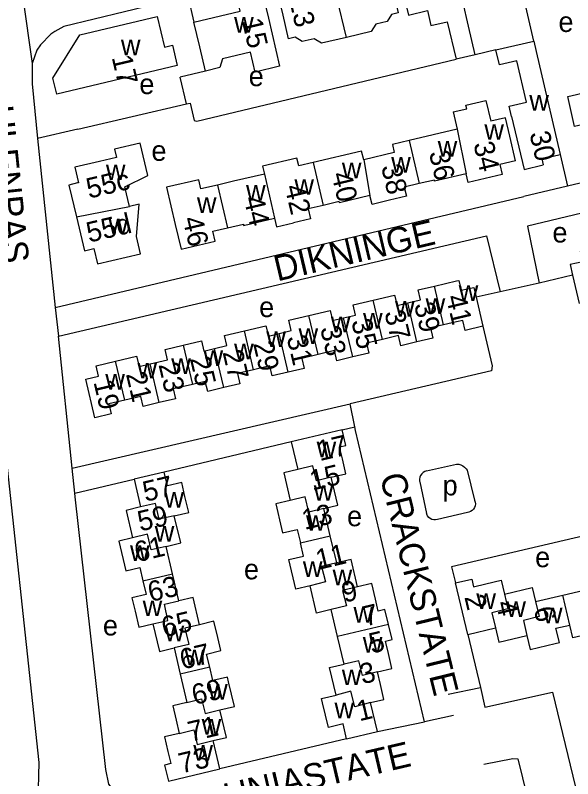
# Model space of a CAD drawing. Extents: x 157646 to 159241, y 379213 to 381217.
# Drawn here: x 158413 to 158522.9, y 380508.3 to 380658.9 of the extents above; entities that cross this region are included whole.
import ezdxf

# ---------------------------------------------------------------- set-up
doc = ezdxf.new("R2010")
doc.units = 0
for name, color, linetype in [('BLT_Basislijn', 7, 'Continuous'), ('BLT_Bebouwing', 7, 'Continuous'), ('BLT_Centroide', 7, 'Continuous'), ('BLT_Huisnummer', 7, 'Continuous'), ('BLT_Huisnummer_ tussenligend', 7, 'Continuous'), ('BLT_Onderverdeling_panden', 7, 'Continuous'), ('BLT_Straatnaam', 7, 'Continuous'), ('BLT_Vlakafsluiter', 7, 'Continuous')]:
    doc.layers.add(name, color=color, linetype=linetype)

msp = doc.modelspace()

# ---------------------------------------------------------------- linework, layer by layer
at = {"layer": 'BLT_Basislijn'}
for p, q in [((158515.2, 380653.77), (158512.79, 380664.6)), ((158447.01, 380662.59), (158448.21, 380657.51)), ((158507.75, 380652.05), (158503.65, 380651.07)), ((158450.49, 380647.86), (158445.49, 380646.66)), ((158446.72, 380641.37), (158445.49, 380646.66)), ((158425.3, 380636.36), (158446.72, 380641.37)), ((158425.3, 380636.36), (158417.35, 380634.52)), ((158417.35, 380634.52), (158420.82, 380601.23)), ((158520.42, 380631.37), (158521.88, 380625.14)), ((158420.82, 380601.23), (158513.28, 380623.09)), ((158522.88, 380607.57), (158516.27, 380606.04)), ((158516.27, 380606.04), (158508.57, 380604.3)), ((158508.57, 380604.3), (158503.84, 380603.23)), ((158420.82, 380601.23), (158421.53, 380595.56)), ((158424.19, 380569.51), (158421.53, 380595.56)), ((158424.19, 380569.51), (158479.03, 380582.24)), ((158479.92, 380577.68), (158479.03, 380582.24)), ((158477.44, 380577.11), (158479.92, 380577.68)), ((158467.41, 380574.73), (158442.32, 380568.77)), ((158424.7, 380564.63), (158424.19, 380569.51)), ((158494.09, 380569.01), (158500, 380570.34)), ((158502.08, 380569.12), (158503.55, 380563.21)), ((158424.7, 380564.63), (158436.4, 380567.37)), ((158492.72, 380566.81), (158494.06, 380560.62)), ((158502.13, 380560.82), (158496.22, 380559.42)), ((158502.23, 380536.73), (158504.69, 380526.29)), ((158498.34, 380524.99), (158504.69, 380526.29)), ((158499.39, 380520.79), (158493.68, 380519.49)), ((158484.38, 380517.58), (158493.68, 380519.49)), ((158478.3, 380516.14), (158453.31, 380510.22))]:
    msp.add_line(p, q, dxfattribs=at)
for points in [[(158447.01, 380662.59), (158446.7, 380662.51), (158440.52, 380661), (158422.54, 380656.66), (158420.79, 380655.65), (158419.96, 380655.15), (158417.95, 380653.03), (158417.26, 380651.95), (158416.28, 380649.31)], [(158416.28, 380649.31), (158416.34, 380645.36), (158417.35, 380634.52)], [(158446.72, 380641.37), (158447.44, 380641.53), (158448.28, 380638.07), (158448.76, 380637.97), (158499.88, 380650.19)], [(158539.21, 380629.26), (158538.5, 380629.1), (158521.88, 380625.14)], [(158521.88, 380625.14), (158513.28, 380623.09)], [(158538.4, 380623.1), (158513.99, 380617.28), (158516.27, 380606.04)], [(158421.53, 380595.56), (158505.88, 380615.34), (158508.57, 380604.3)], [(158505.2, 380597.51), (158507.01, 380589.72), (158506.85, 380588.76), (158479.03, 380582.24)], [(158382, 380486.03), (158394.7, 380478.15), (158397.65, 380476.58), (158401, 380475.76), (158402.65, 380477.1), (158414.74, 380494.85), (158416.53, 380498.98), (158417.47, 380503.76), (158417.68, 380511.48), (158409.95, 380583.17)], [(158493.68, 380519.49), (158480.06, 380576.99), (158479.92, 380577.68)], [(158500, 380570.34), (158500.43, 380570.31), (158500.85, 380570.19), (158501.23, 380570.01), (158501.58, 380569.75), (158501.87, 380569.43), (158502.08, 380569.12)], [(158494.09, 380569.01), (158493.73, 380568.89), (158493.4, 380568.69), (158493.12, 380568.43), (158492.9, 380568.11), (158492.75, 380567.76), (158492.68, 380567.39), (158492.69, 380567), (158492.72, 380566.81)], [(158432.15, 380506.31), (158431.46, 380507.21), (158430.83, 380510.09), (158424.78, 380563.88), (158424.7, 380564.63)], [(158503.55, 380563.21), (158503.66, 380562.86), (158503.69, 380562.49), (158503.65, 380562.12), (158503.52, 380561.78), (158503.33, 380561.46), (158503.07, 380561.2), (158502.76, 380561), (158502.41, 380560.86), (158502.13, 380560.82)], [(158496.22, 380559.42), (158495.86, 380559.35), (158495.49, 380559.36), (158495.13, 380559.44), (158494.8, 380559.6), (158494.51, 380559.83), (158494.28, 380560.12), (158494.12, 380560.45), (158494.06, 380560.62)], [(158534.42, 380558.37), (158533.32, 380558.11), (158498.97, 380550.09), (158499.8, 380546.9)], [(158504.69, 380526.29), (158505.57, 380522.37), (158518.89, 380525.34), (158527.39, 380490.29), (158538.07, 380492.65)], [(158505.34, 380511.18), (158511.1, 380512.31), (158512.05, 380512.19), (158518.7, 380485.21)]]:
    msp.add_lwpolyline(points, dxfattribs=at)
at = {"layer": 'BLT_Bebouwing'}
for p, q in [((158507.75, 380652.05), (158515.2, 380653.77)), ((158515.2, 380653.77), (158515.66, 380651.69)), ((158503.65, 380651.07), (158499.88, 380650.19)), ((158515.66, 380651.69), (158520.42, 380631.37)), ((158499.32, 380639.8), (158501.99, 380640.42)), ((158501.99, 380640.42), (158501.83, 380641.12)), ((158499.32, 380639.8), (158500.13, 380636.36)), ((158510.84, 380638.92), (158513.29, 380628.47)), ((158516.82, 380630.52), (158520.42, 380631.37)), ((158516.82, 380630.52), (158517.09, 380629.36)), ((158513.29, 380628.47), (158517.09, 380629.36)), ((158462.11, 380627.55), (158455.98, 380626.11)), ((158522.88, 380607.57), (158524.19, 380602.04)), ((158503.84, 380603.23), (158505.2, 380597.51)), ((158477.44, 380577.11), (158467.41, 380574.73)), ((158467.41, 380574.73), (158468.69, 380569.29)), ((158442.32, 380568.77), (158436.4, 380567.37)), ((158436.4, 380567.37), (158437.7, 380561.88)), ((158445.24, 380543.4), (158443.99, 380548.68)), ((158502.23, 380536.73), (158499.8, 380546.9)), ((158520.92, 380544.49), (158526.26, 380545.76)), ((158515.58, 380543.21), (158520.92, 380544.49)), ((158476.53, 380536.32), (158475.27, 380541.64)), ((158502.23, 380536.73), (158507.67, 380538.02)), ((158477.82, 380530.89), (158476.53, 380536.32)), ((158444.28, 380534.08), (158445.51, 380528.9)), ((158478.3, 380516.14), (158484.38, 380517.58)), ((158453.31, 380510.22), (158451.99, 380515.8)), ((158443.18, 380507.82), (158453.31, 380510.22))]:
    msp.add_line(p, q, dxfattribs=at)
for points in [[(158503.65, 380651.07), (158502.33, 380656.72), (158501.2, 380661.59), (158500, 380661.31), (158497.74, 380660.78), (158495.35, 380671.01), (158488.06, 380669.31), (158489.2, 380664.44), (158490.49, 380658.89), (158494.25, 380659.77), (158494.94, 380656.81), (158498.16, 380657.56), (158499.88, 380650.19)], [(158476.28, 380662.89), (158478.68, 380663.46), (158479.46, 380664.72), (158479.17, 380665.96), (158480.15, 380667.54), (158486.19, 380668.96), (158487.34, 380664.1), (158488.46, 380659.33), (158487.15, 380659.02), (158486.29, 380657.64), (158484.08, 380657.11), (158483.17, 380655.65), (158478.26, 380654.49)], [(158478.26, 380654.49), (158473.34, 380653.33), (158471.93, 380654.21), (158469.56, 380653.65), (158468.17, 380654.51), (158466.87, 380654.21), (158465.77, 380658.9), (158464.62, 380663.77), (158470.52, 380665.15), (158472.03, 380664.22), (158472.3, 380663.06), (158473.59, 380662.26), (158476.28, 380662.89)], [(158448.21, 380657.51), (158457.33, 380659.66), (158456.78, 380662), (158461.73, 380663.16), (158462.88, 380658.3), (158465.11, 380648.79), (158460.25, 380647.65), (158459.33, 380651.56), (158453.86, 380650.27), (158453.33, 380648.53), (158450.49, 380647.86)], [(158425.69, 380655.01), (158440.98, 380658.64), (158442.41, 380652.57), (158443.97, 380652.93), (158444.93, 380648.96), (158421.15, 380643.31), (158420.39, 380646.45), (158425.69, 380655.01)], [(158450.49, 380647.86), (158449.36, 380652.65), (158448.21, 380657.51)], [(158510.84, 380638.92), (158510.37, 380640.92), (158513.8, 380641.73), (158511.89, 380649.89), (158508.44, 380649.08), (158507.75, 380652.05)], [(158538.75, 380631.2), (158531, 380629.4), (158528.94, 380638.26), (158523.27, 380636.94), (158521.9, 380642.83), (158531.25, 380645)], [(158501.83, 380641.12), (158505.77, 380642.05), (158506.73, 380637.96)], [(158509.62, 380638.63), (158506.73, 380637.96)], [(158511.61, 380630.14), (158510.47, 380635.01), (158509.62, 380638.63)], [(158500.13, 380636.36), (158490.62, 380634.13)], [(158490.62, 380634.13), (158487.34, 380633.36), (158487.71, 380631.78), (158481.68, 380630.35)], [(158434.55, 380624.99), (158439.13, 380627.24), (158437.63, 380633.63), (158432.54, 380632.43), (158432.92, 380630.81)], [(158481.68, 380630.35), (158481.27, 380632.07), (158471.71, 380629.82)], [(158432.92, 380630.81), (158429.57, 380630.03), (158424.7, 380628.88), (158425.42, 380625.83), (158425.23, 380625.78), (158423.55, 380625.38), (158425.02, 380619.1)], [(158471.71, 380629.82), (158468.87, 380629.15), (158468.51, 380630.7), (158461.74, 380629.12), (158462.11, 380627.55)], [(158511.61, 380630.14), (158508.54, 380629.42), (158508.99, 380627.47), (158505.65, 380626.68)], [(158501.86, 380627.59), (158495.62, 380626.12), (158495.66, 380626.36)], [(158505.65, 380626.68), (158502.26, 380625.89), (158501.86, 380627.59)], [(158435.47, 380621.12), (158434.55, 380624.99)], [(158452.84, 380625.37), (158449.59, 380624.6), (158449.16, 380626.43), (158442.8, 380624.93), (158444.53, 380617.57), (158445.68, 380612.71), (158452.4, 380614.29), (158451.94, 380616.25), (158454.81, 380616.92)], [(158455.98, 380626.11), (158452.84, 380625.37)], [(158492.6, 380625.65), (158489.69, 380624.97), (158490.12, 380623.15), (158486.74, 380622.36)], [(158495.66, 380626.36), (158492.59, 380625.65)], [(158476.85, 380622.12), (158473.68, 380621.37)], [(158482.91, 380623.31), (158476.9, 380621.89), (158476.85, 380622.12)], [(158486.74, 380622.36), (158483.33, 380621.55), (158482.91, 380623.31)], [(158425.02, 380619.1), (158426.6, 380612.42), (158428.49, 380612.86), (158429.21, 380609.81), (158437.66, 380611.8), (158436.86, 380615.21), (158437.4, 380621.58), (158435.47, 380621.12)], [(158473.68, 380621.37), (158470.76, 380620.68), (158471.22, 380618.72), (158467.86, 380617.93)], [(158454.81, 380616.92), (158457.97, 380617.67)], [(158457.97, 380617.67), (158458.01, 380617.41), (158464.07, 380618.87)], [(158464.07, 380618.87), (158464.48, 380617.14), (158467.86, 380617.93)], [(158528.35, 380613.18), (158524.39, 380612.24), (158524.86, 380610.25), (158522.38, 380609.67), (158522.88, 380607.57)], [(158490.35, 380602.12), (158492.86, 380602.72), (158492.4, 380604.69), (158495.62, 380605.45)], [(158495.62, 380605.45), (158500, 380606.49), (158500.45, 380606.57), (158500.91, 380604.61), (158503.38, 380605.19), (158503.84, 380603.23)], [(158477.72, 380599.16), (158480.06, 380599.71), (158479.58, 380601.73), (158483.56, 380602.67)], [(158483.56, 380602.67), (158487.77, 380603.67), (158488.25, 380601.63), (158490.35, 380602.12)], [(158464.99, 380596.09), (158467.4, 380596.66), (158466.92, 380598.71), (158470.86, 380599.65)], [(158470.86, 380599.65), (158475.08, 380600.64), (158475.56, 380598.64), (158477.72, 380599.16)], [(158505.2, 380597.51), (158501.71, 380596.68), (158501.24, 380598.65), (158499.99, 380598.4), (158497.43, 380597.79)], [(158452.26, 380593.14), (158454.72, 380593.72), (158454.25, 380595.69), (158458.17, 380596.62)], [(158458.17, 380596.62), (158462.41, 380597.62), (158462.89, 380595.6), (158464.99, 380596.09)], [(158497.43, 380597.79), (158494.86, 380597.18), (158495.33, 380595.19), (158492.17, 380594.44)], [(158485.39, 380594.93), (158482.24, 380594.19), (158482.7, 380592.23), (158479.54, 380591.48)], [(158492.17, 380594.44), (158489, 380593.69), (158488.53, 380595.68), (158485.39, 380594.93)], [(158439.56, 380590.09), (158443, 380590.91), (158442.52, 380592.93), (158446.09, 380593.77)], [(158446.09, 380593.77), (158449.67, 380594.62), (158450.13, 380592.64), (158452.26, 380593.14)], [(158472.68, 380591.94), (158469.47, 380591.18), (158469.93, 380589.21), (158466.8, 380588.46)], [(158479.54, 380591.48), (158476.37, 380590.73), (158475.9, 380592.71), (158472.68, 380591.94)], [(158434.58, 380582.96), (158431.44, 380582.22), (158431.91, 380580.22), (158428.68, 380579.46), (158426.88, 380587.08), (158429.39, 380587.68), (158428.9, 380589.74), (158432.76, 380590.65)], [(158432.76, 380590.65), (158436.9, 380591.63), (158437.39, 380589.58), (158439.56, 380590.09)], [(158459.98, 380588.96), (158456.77, 380588.2), (158457.26, 380586.18), (158454.09, 380585.43)], [(158466.8, 380588.46), (158463.65, 380587.72), (158463.18, 380589.72), (158459.98, 380588.96)], [(158447.92, 380586.06), (158444.08, 380585.15), (158444.54, 380583.21), (158441.36, 380582.46)], [(158454.09, 380585.43), (158450.92, 380584.68), (158450.45, 380586.66), (158447.92, 380586.06)], [(158441.36, 380582.46), (158438.19, 380581.71), (158437.72, 380583.7), (158434.58, 380582.96)], [(158477.47, 380571.37), (158476.91, 380573.72), (158478.17, 380574.02), (158477.44, 380577.11)], [(158475.29, 380567.73), (158478.17, 380568.41), (158477.47, 380571.37)], [(158468.69, 380569.29), (158465.9, 380568.63), (158467.18, 380563.19)], [(158446.44, 380563.95), (158445.79, 380566.69), (158442.97, 380566.02), (158442.32, 380568.77)], [(158473.82, 380561.57), (158476.59, 380562.23), (158475.29, 380567.73)], [(158444.33, 380560.15), (158447.18, 380560.82), (158446.44, 380563.95)], [(158467.18, 380563.19), (158464.33, 380562.52), (158465.48, 380557.65), (158465.69, 380556.76), (158468.57, 380557.45), (158469.19, 380554.83)], [(158437.7, 380561.88), (158434.82, 380561.2), (158436.1, 380555.81)], [(158475.09, 380556.22), (158473.82, 380561.57)], [(158442.7, 380554.11), (158445.6, 380554.8), (158444.33, 380560.15)], [(158436.1, 380555.81), (158433.38, 380555.16), (158434.77, 380549.29), (158437.52, 380549.94), (158438.15, 380547.29)], [(158476.36, 380550.88), (158475.09, 380556.22)], [(158471.12, 380546.34), (158468.29, 380545.67), (158466.9, 380551.52), (158469.81, 380552.21), (158469.19, 380554.83)], [(158443.99, 380548.68), (158442.7, 380554.11)], [(158480.47, 380546.12), (158479.18, 380551.55), (158476.36, 380550.88)], [(158438.15, 380547.29), (158438.77, 380544.65), (158435.98, 380543.99), (158436.6, 380541.35)], [(158484, 380543.7), (158483.27, 380546.78), (158480.47, 380546.12)], [(158499.8, 380546.9), (158502.97, 380547.64), (158503.32, 380546.16), (158505.74, 380546.74)], [(158505.74, 380546.74), (158508.77, 380547.46), (158509.43, 380544.68)], [(158475.27, 380541.64), (158472.39, 380540.96), (158471.12, 380546.34)], [(158509.43, 380544.68), (158514.92, 380545.99), (158515.58, 380543.21)], [(158449.32, 380538.66), (158448.05, 380544.06), (158445.24, 380543.4)], [(158486.57, 380538.7), (158485.87, 380541.63), (158484.56, 380541.33), (158484, 380543.7)], [(158436.6, 380541.35), (158437.36, 380538.17), (158440.11, 380538.83)], [(158452.92, 380536.12), (158452.16, 380539.33), (158449.32, 380538.66)], [(158530.6, 380540.6), (158531.27, 380537.77), (158525.56, 380536.4), (158525.49, 380536.67), (158522.93, 380536.08), (158522.32, 380538.6)], [(158440.11, 380538.83), (158441.4, 380533.39), (158444.28, 380534.08)], [(158486.56, 380532.96), (158485.97, 380535.45), (158487.26, 380535.76), (158486.57, 380538.7)], [(158507.67, 380538.02), (158508.33, 380535.24), (158513.87, 380536.55)], [(158513.87, 380536.55), (158514.53, 380533.76), (158519.4, 380534.93), (158520.27, 380535.13), (158519.59, 380537.95), (158522.32, 380538.6)], [(158451.33, 380530.28), (158450.71, 380532.88), (158453.53, 380533.55), (158452.92, 380536.12)], [(158484.38, 380529.36), (158487.25, 380530.04), (158486.56, 380532.96)], [(158453.32, 380521.86), (158456.18, 380522.54), (158455.02, 380527.4), (158454.8, 380528.35), (158451.94, 380527.67), (158451.33, 380530.28)], [(158476.24, 380524.78), (158474.96, 380530.21), (158477.82, 380530.89)], [(158445.51, 380528.9), (158446.82, 380523.35)], [(158484.97, 380526.85), (158484.38, 380529.36)], [(158483.03, 380523.29), (158485.67, 380523.91), (158484.97, 380526.85)], [(158478.3, 380516.14), (158477.6, 380519.09), (158474.71, 380518.4), (158473.56, 380523.27), (158473.36, 380524.1), (158476.24, 380524.78)], [(158446.82, 380523.35), (158444.02, 380522.68), (158444.7, 380519.82)], [(158484.38, 380517.58), (158483.03, 380523.29)], [(158451.99, 380515.8), (158454.61, 380516.43), (158453.32, 380521.86)], [(158444.7, 380519.82), (158445.32, 380517.21)], [(158445.32, 380517.21), (158442.39, 380516.52), (158443.06, 380513.69)], [(158443.06, 380513.69), (158443.63, 380511.29), (158442.41, 380510.99), (158443.18, 380507.82)]]:
    msp.add_lwpolyline(points, dxfattribs=at)
at = {"layer": 'BLT_Onderverdeling_panden'}
for p, q in [((158478.26, 380654.49), (158476.28, 380662.89)), ((158500.13, 380636.36), (158501.86, 380627.59)), ((158490.62, 380634.13), (158492.6, 380625.65)), ((158471.71, 380629.82), (158473.68, 380621.37)), ((158481.68, 380630.35), (158482.91, 380623.31)), ((158462.11, 380627.55), (158464.07, 380618.87)), ((158452.84, 380625.37), (158454.81, 380616.92)), ((158425.02, 380619.1), (158435.47, 380621.12)), ((158497.43, 380597.79), (158495.62, 380605.45)), ((158485.39, 380594.93), (158483.56, 380602.67)), ((158492.17, 380594.44), (158490.35, 380602.12)), ((158472.68, 380591.94), (158470.86, 380599.65)), ((158479.54, 380591.48), (158477.72, 380599.16)), ((158459.98, 380588.96), (158458.17, 380596.62)), ((158466.8, 380588.46), (158464.99, 380596.09)), ((158446.09, 380593.77), (158447.92, 380586.06)), ((158454.09, 380585.43), (158452.26, 380593.14)), ((158434.58, 380582.96), (158432.76, 380590.65)), ((158441.36, 380582.46), (158439.56, 380590.09)), ((158469.19, 380554.83), (158475.09, 380556.22)), ((158438.15, 380547.29), (158443.99, 380548.68)), ((158522.32, 380538.6), (158520.92, 380544.49)), ((158486.57, 380538.7), (158476.53, 380536.32)), ((158451.33, 380530.28), (158445.51, 380528.9))]:
    msp.add_line(p, q, dxfattribs=at)
for points in [[(158475.29, 380567.73), (158472.4, 380567.01), (158471.64, 380569.99), (158468.69, 380569.29)], [(158473.82, 380561.57), (158470.86, 380560.87), (158470.14, 380563.9), (158467.18, 380563.19)], [(158444.33, 380560.15), (158441.38, 380559.45), (158440.65, 380562.57), (158437.7, 380561.88)], [(158442.7, 380554.11), (158439.76, 380553.42), (158439.03, 380556.5), (158436.1, 380555.81)], [(158476.36, 380550.88), (158473.37, 380550.17), (158474.12, 380547.11), (158471.12, 380546.34)], [(158480.47, 380546.12), (158477.51, 380545.41), (158478.26, 380542.41), (158475.27, 380541.64)], [(158509.43, 380544.68), (158510.13, 380541.77), (158506.95, 380541.02), (158507.67, 380538.02)], [(158440.11, 380538.83), (158443.05, 380539.52), (158442.41, 380542.73), (158445.24, 380543.4)], [(158515.58, 380543.21), (158516.29, 380540.26), (158513.16, 380539.51), (158513.87, 380536.55)], [(158449.32, 380538.66), (158446.42, 380537.98), (158447.18, 380534.76), (158444.28, 380534.08)], [(158484.38, 380529.36), (158481.45, 380528.66), (158480.73, 380531.56), (158477.82, 380530.89)], [(158483.03, 380523.29), (158479.95, 380522.49), (158479.15, 380525.53), (158476.24, 380524.78)], [(158446.82, 380523.35), (158449.73, 380524.03), (158450.41, 380521.17), (158453.32, 380521.86)], [(158445.32, 380517.21), (158448.2, 380517.9), (158448.87, 380515.07), (158451.99, 380515.8)]]:
    msp.add_lwpolyline(points, dxfattribs=at)
at = {"layer": 'BLT_Vlakafsluiter'}
msp.add_line((158413.47, 380669.54), (158416.28, 380649.31), dxfattribs=at)

# ---------------------------------------------------------------- texts
at = {"layer": 'BLT_Centroide'}
for s, p in [('w', (158456.13, 380655.41)), ('e', (158520.08, 380655.56)), ('w', (158433.81, 380650.97)), ('e', (158459, 380644.87)), ('e', (158437.44, 380643.31)), ('w', (158514.33, 380640.05)), ('w', (158505.47, 380634.3)), ('w', (158496.27, 380631)), ('e', (158439.83, 380630.15)), ('w', (158477.38, 380626.72)), ('w', (158487.1, 380627.84)), ('w', (158430.85, 380626.34)), ('w', (158468.02, 380623.45)), ('w', (158458.48, 380622.28)), ('w', (158448.8, 380619.89)), ('w', (158431.36, 380615.69)), ('e', (158518.89, 380614.04)), ('w', (158500.41, 380602.52)), ('e', (158461.06, 380599.33)), ('w', (158487.86, 380599.41)), ('w', (158493.89, 380599.94)), ('w', (158475.2, 380596.34)), ('w', (158481.55, 380597.08)), ('w', (158462.48, 380593.44)), ('w', (158468.83, 380594.05)), ('w', (158456.12, 380591.02)), ('w', (158450.09, 380589.69)), ('w', (158437.06, 380587.23)), ('w', (158443.73, 380588.12)), ('w', (158430.73, 380585.05)), ('w', (158472.4, 380571.7)), ('p', (158497.24, 380564.16)), ('w', (158442.37, 380561.75)), ('w', (158471.83, 380563.1)), ('w', (158470.3, 380557.18)), ('e', (158478.4, 380558.08)), ('w', (158440.48, 380555.05)), ('w', (158435.6, 380551.26)), ('e', (158515.48, 380550)), ('w', (158469.69, 380548.09)), ('e', (158458.07, 380547.61)), ('w', (158475.55, 380546.45)), ('w', (158503.89, 380541.75)), ('w', (158438.1, 380540.35)), ('w', (158479.67, 380539.07)), ('w', (158509.8, 380540.19)), ('w', (158517.02, 380538.95)), ('e', (158430.26, 380536.54)), ('w', (158442.43, 380535.41)), ('w', (158481.51, 380533.15)), ('w', (158446.39, 380530.65)), ('w', (158477.37, 380526.74)), ('w', (158451, 380523.88)), ('w', (158475.92, 380520.22)), ('w', (158449.73, 380516.99)), ('w', (158448.09, 380511.84))]:
    msp.add_text(s, height=4, dxfattribs=at).set_placement(p)
at = {"layer": 'BLT_Huisnummer'}
for s, rotation, p in [('13', 283.2405, (158466.93, 380661.99)), ('15', 283.2532, (158457.63, 380657.83)), ('17', 283.2532, (158431.97, 380650.57)), ('30', 283.195, (158514.34, 380635.55)), ('34', 283.2, (158503.29, 380633.51)), ('38', 283.2625, (158485.1, 380629.01)), ('55c', 13.2497, (158427.5, 380622.68)), ('42', 283.2541, (158466.06, 380625.04)), ('55d', 13.2469, (158427.52, 380614)), ('46', 283.2609, (158445.94, 380618.73)), ('41', 283.3146, (158497.86, 380603.31)), ('35', 283.3146, (158479.21, 380598.52)), ('31', 283.3146, (158466.47, 380595.32)), ('27', 283.3146, (158453.83, 380592.41)), ('23', 283.3146, (158441.2, 380589.96)), ('19', 283.3146, (158428.38, 380586.53)), ('17', 13.3242, (158473.01, 380570.91)), ('57', 13.3206, (158438.64, 380562.88)), ('13', 13.3146, (158470.02, 380557.35)), ('61', 13.328, (158436.99, 380550.97)), ('9', 13.3128, (158477.86, 380542.99)), ('2', 283.4492, (158501.51, 380544.14)), ('6', 283.4492, (158515.18, 380541.79)), ('65', 13.3201, (158442.34, 380536.17)), ('5', 13.3128, (158483.23, 380532.96)), ('69', 13.3194, (158448.3, 380522.82)), ('1', 13.3173, (158480.82, 380519.6)), ('73', 13.3187, (158445.71, 380509.3))]:
    msp.add_text(s, height=4, rotation=rotation, dxfattribs=at).set_placement(p)
at = {"layer": 'BLT_Huisnummer_ tussenligend'}
for s, rotation, p in [('36', 283.2036, (158494.52, 380631.76)), ('40', 283.2625, (158475.29, 380627.51)), ('44', 283.2541, (158457.98, 380622.77)), ('39', 283.3146, (158491.59, 380601.79)), ('37', 283.3146, (158485.74, 380600.25)), ('33', 283.3146, (158473.07, 380597.14)), ('29', 283.3146, (158459.86, 380594.12)), ('25', 283.3146, (158447.39, 380591.16)), ('21', 283.3146, (158434.78, 380588.09)), ('15', 13.3146, (158471.57, 380565.1)), ('59', 13.3206, (158437.62, 380557.03)), ('11', 13.3128, (158472.75, 380549.46)), ('63', 13.328, (158439.65, 380543.12)), ('7', 13.3128, (158482.01, 380538.29)), ('4', 283.4492, (158507.7, 380542.95)), ('67', 13.3201, (158445.94, 380529.8)), ('3', 13.3173, (158481.42, 380526.9)), ('71', 13.3194, (158447.54, 380515.53))]:
    msp.add_text(s, height=4, rotation=rotation, dxfattribs=at).set_placement(p)
at = {"layer": 'BLT_Straatnaam'}
for s, rotation, p in [('ULENPAS', 275.9474, (158407.55, 380640.82)), ('DIKNINGE', 13.2468, (158464.65, 380606.35)), ('CRACKSTATE', 283.8613, (158484.84, 380567.96)), ('UNIASTATE', 13.1222, (158454.77, 380502.31))]:
    msp.add_text(s, height=5, rotation=rotation, dxfattribs=at).set_placement(p)

doc.saveas('drawing.dxf')
